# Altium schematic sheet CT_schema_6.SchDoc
size 226 x 144 mm
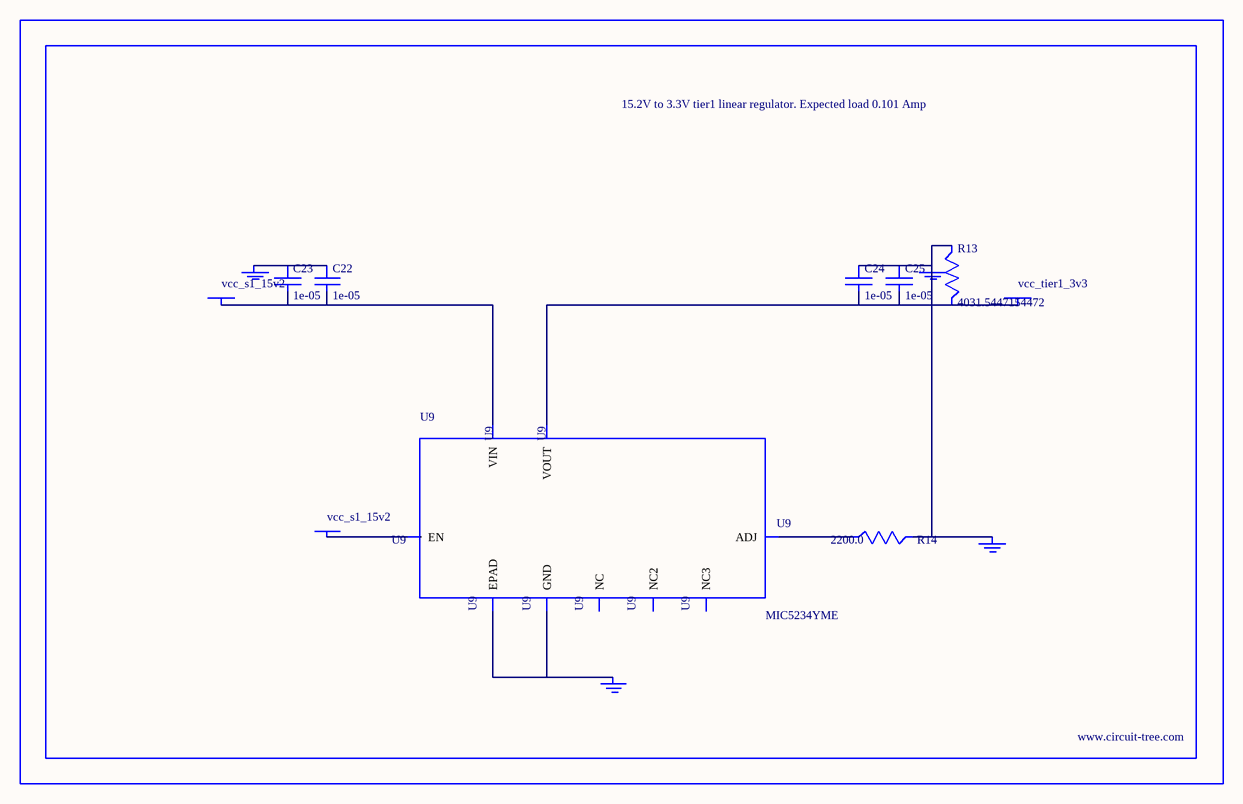
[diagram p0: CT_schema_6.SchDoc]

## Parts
BORDER5  (no value)
C22  1e-05  [C1210]
C23  1e-05  [C1210]
C24  1e-05  [C1210]
C25  1e-05  [C1210]
GND_INSTANCE_5_0  (no value)
GND_INSTANCE_5_1  (no value)
GND_INSTANCE_5_2  (no value)
GND_INSTANCE_5_3  (no value)
POWER_INSTANCE_5_0  vcc_tier1_3v3
POWER_INSTANCE_5_1  vcc_s1_15v2
POWER_INSTANCE_5_2  vcc_s1_15v2
R13  4031.5447154472  [R0603]
R14  2200.0  [R0603]
U9  MIC5234YME  [SOIC-8_EP]

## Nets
NetC22_1: C22.1 C23.1 GND_INSTANCE_5_3.0(GND)
NetC22_2: C22.2 C23.2 POWER_INSTANCE_5_2.0(PWR) U9.8(VIN)
NetC24_1: C24.1 C25.1 GND_INSTANCE_5_0.0(GND) GND_INSTANCE_5_1.0(GND) R13.1 R14.2
NetC24_2: C24.2 C25.2 POWER_INSTANCE_5_0.0(PWR) R13.2 U9.1(VOUT)
NetGND_INSTANCE_5_2_0: GND_INSTANCE_5_2.0(GND) U9.7(GND) U9.EPAD
NetPOWER_INSTANCE_5_1_0: POWER_INSTANCE_5_1.0(PWR) U9.5(EN)
NetR14_1: R14.1 U9.4(ADJ)

Not connected (* = marked no-connect by the designer): U9 2(NC) 3(NC2) 6(NC3)

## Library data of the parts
BORDER5 = BORDER_PAGE5
C22-C25 = C1210C106K5PACTU
GND_INSTANCE_5_0-GND_INSTANCE_5_3 = GND
POWER_INSTANCE_5_0-POWER_INSTANCE_5_2 = PWR
R13 = R13
R14 = RC0603JR-072K2L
